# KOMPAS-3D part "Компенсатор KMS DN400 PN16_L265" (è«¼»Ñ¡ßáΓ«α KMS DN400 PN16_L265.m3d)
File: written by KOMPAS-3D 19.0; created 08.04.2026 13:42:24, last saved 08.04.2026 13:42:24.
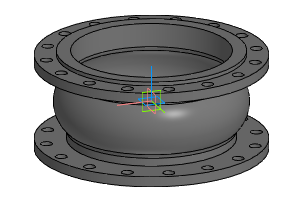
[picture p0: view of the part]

Document properties: Автор: Энергия; Полное имя файла: Z:\3.Личные\kachalov\3d для проектировщиков\7.1 Компенсатор\stp_Компенсатор KSM\Компенсатор KMS DN400 PN16_L265.m3d

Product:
- Part/product: Компенсатор KMS DN400 PN16_L265

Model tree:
1. Операция без истории:1  (labels: Компенсатор KMS DN400 PN16_L265)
